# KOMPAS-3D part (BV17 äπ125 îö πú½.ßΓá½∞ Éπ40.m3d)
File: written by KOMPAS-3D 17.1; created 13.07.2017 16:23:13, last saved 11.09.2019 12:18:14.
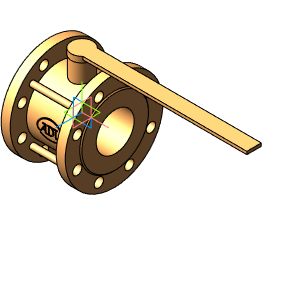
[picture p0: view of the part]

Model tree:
1. Операция без истории:2  (labels: Сталь 20  ГОСТ 1050-88)

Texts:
  DISO1
  DISO2
  BV17 Ду10 ФФ Ру40 угл. сталь
  BV17 Ду15 ФФ Ру40 угл. сталь
  BV17 Ду20 ФФ Ру40 угл. сталь
  BV17 Ду25 ФФ Ру40 угл. сталь
  BV17 Ду32 ФФ Ру40 угл. сталь
  BV17 Ду40 ФФ Ру40 угл. сталь
  BV17 Ду50 ФФ Ру40 угл. сталь
  BV17 Ду65 ФФ Ру40 угл. сталь
  BV17 Ду80 ФФ Ру40 угл. сталь
  BV17 Ду100 ФФ Ру40 угл. сталь
  BV17 Ду125 ФФ Ру40 угл. сталь
  BV17 Ду150 ФФ Ру40 угл. сталь
  BV17 Ду200 ФФ Ру40 угл. сталь
  BV17 Ду250 ФФ Ру40 угл. сталь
